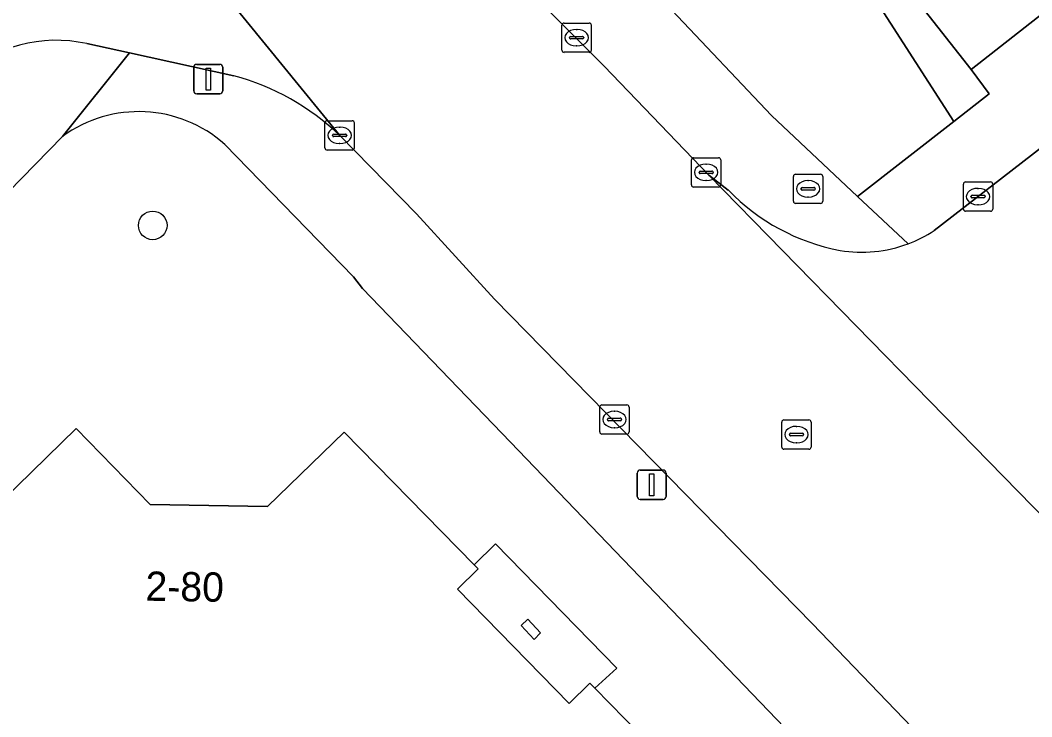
# Model space of a CAD drawing. Extents: x 159217 to 160349, y 381246 to 382172.
# Drawn here: x 159551.64 to 159586.14, y 381526.69 to 381550.47 of the extents above; entities that cross this region are included whole.
import ezdxf

# ---------------------------------------------------------------- set-up
doc = ezdxf.new("R2010")
doc.units = 0
for name, color, linetype in [('IMGEO_Boom', 7, 'Continuous'), ('IMGEO_Brandkraan', 7, 'Continuous'), ('IMGEO_Erf', 7, 'Continuous'), ('IMGEO_Fietspad_gesloten', 7, 'Continuous'), ('IMGEO_Groenvoorziening', 7, 'Continuous'), ('IMGEO_Haag', 7, 'Continuous'), ('IMGEO_Kolk', 7, 'Continuous'), ('IMGEO_Lichtmast', 7, 'Continuous'), ('IMGEO_Pand', 7, 'Continuous'), ('IMGEO_Pand_nummerreeks', 7, 'Continuous'), ('IMGEO_Rijbaan_lokaal_gesloten', 7, 'Continuous'), ('IMGEO_Rijbaan_lokaal_open', 7, 'Continuous'), ('IMGEO_Rioolput', 7, 'Continuous'), ('IMGEO_Voetpad_open', 7, 'Continuous')]:
    doc.layers.add(name, color=color, linetype=linetype)

msp = doc.modelspace()

# ---------------------------------------------------------------- linework, layer by layer
at = {"layer": 'IMGEO_Boom'}
msp.add_circle((159556.157, 381543.464), 0.489, dxfattribs=at)
at = {"layer": 'IMGEO_Brandkraan'}
for p, q in [((159578.01, 381544.286), (159578.01, 381545.138)), ((159578.085, 381545.212), (159578.937, 381545.212)), ((159578.498, 381544.992), (159578.523, 381544.992)), ((159579.011, 381545.138), (159579.011, 381544.286)), ((159578.269, 381544.706), (159578.269, 381544.718)), ((159578.707, 381544.669), (159578.309, 381544.669)), ((159578.312, 381544.755), (159578.71, 381544.755)), ((159578.753, 381544.718), (159578.753, 381544.706)), ((159578.937, 381544.212), (159578.085, 381544.212)), ((159578.521, 381544.432), (159578.496, 381544.432))]:
    msp.add_line(p, q, dxfattribs=at)
for points in [[(159578.01, 381544.286), (159578.01, 381545.138)], [(159578.085, 381545.212), (159578.937, 381545.212)], [(159579.011, 381545.138), (159579.011, 381544.286)], [(159578.937, 381544.212), (159578.085, 381544.212)]]:
    msp.add_lwpolyline(points, dxfattribs=at)
for centre, radius, start, end in [((159578.087, 381545.136), 0.0765, 91.552, 178.448), ((159578.087, 381545.136), 0.0765, 91.552, 178.448), ((159578.935, 381545.136), 0.0765, 1.552, 88.448), ((159578.935, 381545.136), 0.0765, 1.552, 88.448), ((159578.309, 381544.715), 0.0403, 85.8775, 175.7526), ((159578.306, 381544.705), 0.0366, 178.938, 274.7102), ((159578.71, 381544.712), 0.043, 264.8664, 352.4533), ((159578.714, 381544.717), 0.0386, 1.7309, 96.639), ((159578.087, 381544.288), 0.0765, 181.552, 268.448), ((159578.087, 381544.288), 0.0765, 181.552, 268.448), ((159578.935, 381544.288), 0.0765, 271.552, 358.448), ((159578.935, 381544.288), 0.0765, 271.552, 358.448)]:
    msp.add_arc(centre, radius, start, end, dxfattribs=at)
for centre, major_axis, ratio, start_param, end_param in [((159578.497, 381544.712), (-0.387, 0.002), 0.722429, 4.712389, 7.853982), ((159578.522, 381544.712), (-0.39, 0.002), 0.717154, 1.570796, 4.712389)]:
    msp.add_ellipse(centre, major_axis=major_axis, ratio=ratio, start_param=start_param, end_param=end_param, dxfattribs=at)
at = {"layer": 'IMGEO_Erf'}
for points in [[(159553.08, 381546.504), (159547.055, 381540.335)], [(159599.397, 381500), (159599.498, 381500.339), (159599.569, 381500.686), (159599.609, 381501.038), (159599.616, 381501.392), (159599.593, 381501.746), (159599.537, 381502.095), (159599.451, 381502.439), (159599.334, 381502.773), (159599.188, 381503.096), (159599.014, 381503.404), (159598.813, 381503.695), (159598.586, 381503.968), (159598.538, 381504.02), (159597.784, 381504.824), (159590.258, 381513.08), (159579.357, 381524.607), (159568.355, 381536.063), (159563.311, 381541.305), (159563.005, 381541.713), (159558.611, 381546.23)], [(159549.012, 381532.1), (159553.55, 381536.531), (159556.072, 381533.93), (159560.073, 381533.872), (159562.681, 381536.409), (159567.124, 381531.873), (159567.853, 381532.593), (159571.987, 381528.35), (159571.239, 381527.664), (159579.938, 381518.763), (159579.276, 381518.08), (159583.114, 381514.253), (159583.728, 381514.876), (159588.153, 381510.339), (159588.919, 381511.059), (159590.957, 381508.968), (159590.2, 381508.265), (159594.596, 381503.795)]]:
    msp.add_lwpolyline(points, dxfattribs=at)
for points in [[(159567.853, 381532.593), (159567.124, 381531.873), (159567.256, 381531.738), (159566.553, 381531.041), (159570.364, 381527.142), (159571.07, 381527.837), (159571.239, 381527.664), (159571.987, 381528.35)], [(159568.955, 381530.016), (159569.389, 381529.552), (159569.166, 381529.324), (159568.721, 381529.802)]]:
    msp.add_lwpolyline(points, close=True, dxfattribs=at)
msp.add_arc((159555.676, 381542.937), 4.411, 48.2858, 126.0421, dxfattribs=at)
at = {"layer": 'IMGEO_Fietspad_gesloten'}
for points in [[(159562.533, 381546.538), (159558.685, 381551.263)], [(159553.908, 381549.669), (159555.359, 381549.351), (159558.919, 381548.568)]]:
    msp.add_lwpolyline(points, dxfattribs=at)
for centre, radius, start, end in [((159552.866, 381545.016), 4.769, 77.3835, 133.0545), ((159556.823, 381540.604), 8.235, 46.1004, 75.2534)]:
    msp.add_arc(centre, radius, start, end, dxfattribs=at)
at = {"layer": 'IMGEO_Groenvoorziening'}
for points in [[(159576.056, 381556.935), (159580.454, 381551.717), (159583.479, 381547.014), (159584.683, 381547.956), (159584.068, 381548.786), (159577.496, 381557.149), (159577.049, 381557.715)], [(159573.858, 381550.817), (159577.265, 381547.216), (159580.2, 381544.451), (159583.479, 381547.014), (159580.454, 381551.717), (159576.056, 381556.935), (159573.741, 381555.137), (159571.415, 381553.33)]]:
    msp.add_lwpolyline(points, close=True, dxfattribs=at)
at = {"layer": 'IMGEO_Haag'}
for points in [[(159553.08, 381546.504), (159547.055, 381540.335)], [(159599.397, 381500), (159599.498, 381500.339), (159599.569, 381500.686), (159599.609, 381501.038), (159599.616, 381501.392), (159599.593, 381501.746), (159599.537, 381502.095), (159599.451, 381502.439), (159599.334, 381502.773), (159599.188, 381503.096), (159599.014, 381503.404), (159598.813, 381503.695), (159598.586, 381503.968), (159598.538, 381504.02), (159597.784, 381504.824), (159590.258, 381513.08), (159579.357, 381524.607), (159568.355, 381536.063), (159563.311, 381541.305), (159563.005, 381541.713), (159558.611, 381546.23)], [(159549.012, 381532.1), (159553.55, 381536.531), (159556.072, 381533.93), (159560.073, 381533.872), (159562.681, 381536.409), (159567.124, 381531.873), (159567.853, 381532.593), (159571.987, 381528.35), (159571.239, 381527.664), (159579.938, 381518.763), (159579.276, 381518.08), (159583.114, 381514.253), (159583.728, 381514.876), (159588.153, 381510.339), (159588.919, 381511.059), (159590.957, 381508.968), (159590.2, 381508.265), (159594.596, 381503.795)]]:
    msp.add_lwpolyline(points, dxfattribs=at)
msp.add_arc((159555.676, 381542.937), 4.411, 48.2858, 126.0421, dxfattribs=at)
at = {"layer": 'IMGEO_Kolk'}
for p, q in [((159570.116, 381549.447), (159570.116, 381550.299)), ((159570.191, 381550.373), (159571.043, 381550.373)), ((159570.604, 381550.153), (159570.629, 381550.153)), ((159571.117, 381550.299), (159571.117, 381549.447)), ((159570.375, 381549.867), (159570.375, 381549.879)), ((159570.813, 381549.83), (159570.415, 381549.83)), ((159570.418, 381549.916), (159570.816, 381549.916)), ((159570.859, 381549.879), (159570.859, 381549.867)), ((159570.627, 381549.593), (159570.602, 381549.593)), ((159571.043, 381549.373), (159570.191, 381549.373)), ((159562.107, 381547.038), (159562.959, 381547.038)), ((159562.032, 381546.112), (159562.032, 381546.964)), ((159562.52, 381546.818), (159562.545, 381546.818)), ((159563.033, 381546.964), (159563.033, 381546.112)), ((159562.291, 381546.532), (159562.291, 381546.544)), ((159562.729, 381546.495), (159562.331, 381546.495)), ((159562.334, 381546.581), (159562.732, 381546.581)), ((159562.775, 381546.544), (159562.775, 381546.532)), ((159562.959, 381546.038), (159562.107, 381546.038)), ((159562.543, 381546.258), (159562.518, 381546.258)), ((159574.532, 381544.849), (159574.532, 381545.701)), ((159574.607, 381545.775), (159575.459, 381545.775)), ((159575.533, 381545.701), (159575.533, 381544.849)), ((159574.791, 381545.269), (159574.791, 381545.281)), ((159574.834, 381545.318), (159575.232, 381545.318)), ((159575.02, 381545.555), (159575.045, 381545.555)), ((159575.275, 381545.281), (159575.275, 381545.269)), ((159575.229, 381545.232), (159574.831, 381545.232)), ((159575.043, 381544.995), (159575.018, 381544.995)), ((159583.882, 381544.948), (159584.734, 381544.948)), ((159575.459, 381544.775), (159574.607, 381544.775)), ((159583.807, 381544.022), (159583.807, 381544.874)), ((159584.295, 381544.728), (159584.32, 381544.728)), ((159584.808, 381544.874), (159584.808, 381544.022)), ((159584.066, 381544.442), (159584.066, 381544.454)), ((159584.504, 381544.405), (159584.106, 381544.405)), ((159584.109, 381544.491), (159584.507, 381544.491)), ((159584.55, 381544.454), (159584.55, 381544.442)), ((159584.734, 381543.948), (159583.882, 381543.948)), ((159584.318, 381544.168), (159584.293, 381544.168)), ((159571.481, 381537.338), (159572.333, 381537.338)), ((159571.406, 381536.412), (159571.406, 381537.264)), ((159571.894, 381537.118), (159571.919, 381537.118)), ((159572.407, 381537.264), (159572.407, 381536.412)), ((159571.665, 381536.832), (159571.665, 381536.844)), ((159572.103, 381536.795), (159571.705, 381536.795)), ((159571.708, 381536.881), (159572.106, 381536.881)), ((159572.149, 381536.844), (159572.149, 381536.832)), ((159572.333, 381536.338), (159571.481, 381536.338)), ((159571.917, 381536.558), (159571.892, 381536.558))]:
    msp.add_line(p, q, dxfattribs=at)
for points in [[(159570.116, 381549.447), (159570.116, 381550.299)], [(159570.191, 381550.373), (159571.043, 381550.373)], [(159571.117, 381550.299), (159571.117, 381549.447)], [(159571.043, 381549.373), (159570.191, 381549.373)], [(159562.107, 381547.038), (159562.959, 381547.038)], [(159562.032, 381546.112), (159562.032, 381546.964)], [(159563.033, 381546.964), (159563.033, 381546.112)], [(159562.959, 381546.038), (159562.107, 381546.038)], [(159574.532, 381544.849), (159574.532, 381545.701)], [(159574.607, 381545.775), (159575.459, 381545.775)], [(159575.533, 381545.701), (159575.533, 381544.849)], [(159583.882, 381544.948), (159584.734, 381544.948)], [(159575.459, 381544.775), (159574.607, 381544.775)], [(159583.807, 381544.022), (159583.807, 381544.874)], [(159584.808, 381544.874), (159584.808, 381544.022)], [(159584.734, 381543.948), (159583.882, 381543.948)], [(159571.481, 381537.338), (159572.333, 381537.338)], [(159571.406, 381536.412), (159571.406, 381537.264)], [(159572.407, 381537.264), (159572.407, 381536.412)], [(159572.333, 381536.338), (159571.481, 381536.338)]]:
    msp.add_lwpolyline(points, dxfattribs=at)
for centre, radius, start, end in [((159570.193, 381550.297), 0.0765, 91.552, 178.448), ((159570.193, 381550.297), 0.0765, 91.552, 178.448), ((159571.041, 381550.297), 0.0765, 1.552, 88.448), ((159571.041, 381550.297), 0.0765, 1.552, 88.448), ((159570.415, 381549.876), 0.0403, 85.8775, 175.7526), ((159570.412, 381549.866), 0.0366, 178.938, 274.7102), ((159570.816, 381549.873), 0.043, 264.8664, 352.4533), ((159570.82, 381549.878), 0.0386, 1.7309, 96.639), ((159570.193, 381549.449), 0.0765, 181.552, 268.448), ((159570.193, 381549.449), 0.0765, 181.552, 268.448), ((159571.041, 381549.449), 0.0765, 271.552, 358.448), ((159571.041, 381549.449), 0.0765, 271.552, 358.448), ((159562.109, 381546.962), 0.0765, 91.552, 178.448), ((159562.109, 381546.962), 0.0765, 91.552, 178.448), ((159562.957, 381546.962), 0.0765, 1.552, 88.448), ((159562.957, 381546.962), 0.0765, 1.552, 88.448), ((159562.331, 381546.541), 0.0403, 85.8775, 175.7526), ((159562.328, 381546.531), 0.0366, 178.938, 274.7102), ((159562.732, 381546.538), 0.043, 264.8664, 352.4533), ((159562.736, 381546.543), 0.0386, 1.7309, 96.639), ((159562.109, 381546.114), 0.0765, 181.552, 268.448), ((159562.109, 381546.114), 0.0765, 181.552, 268.448), ((159562.957, 381546.114), 0.0765, 271.552, 358.448), ((159562.957, 381546.114), 0.0765, 271.552, 358.448), ((159574.609, 381545.699), 0.0765, 91.552, 178.448), ((159574.609, 381545.699), 0.0765, 91.552, 178.448), ((159575.457, 381545.699), 0.0765, 1.552, 88.448), ((159575.457, 381545.699), 0.0765, 1.552, 88.448), ((159574.831, 381545.278), 0.0403, 85.8775, 175.7526), ((159574.828, 381545.268), 0.0366, 178.938, 274.7102), ((159575.232, 381545.275), 0.043, 264.8664, 352.4533), ((159575.236, 381545.28), 0.0386, 1.7309, 96.639), ((159583.884, 381544.872), 0.0765, 91.552, 178.448), ((159583.884, 381544.872), 0.0765, 91.552, 178.448), ((159584.732, 381544.872), 0.0765, 1.552, 88.448), ((159584.732, 381544.872), 0.0765, 1.552, 88.448), ((159574.609, 381544.851), 0.0765, 181.552, 268.448), ((159574.609, 381544.851), 0.0765, 181.552, 268.448), ((159575.457, 381544.851), 0.0765, 271.552, 358.448), ((159575.457, 381544.851), 0.0765, 271.552, 358.448), ((159584.106, 381544.451), 0.0403, 85.8775, 175.7526), ((159584.103, 381544.441), 0.0366, 178.938, 274.7102), ((159584.507, 381544.448), 0.043, 264.8664, 352.4533), ((159584.511, 381544.453), 0.0386, 1.7309, 96.639), ((159583.884, 381544.024), 0.0765, 181.552, 268.448), ((159583.884, 381544.024), 0.0765, 181.552, 268.448), ((159584.732, 381544.024), 0.0765, 271.552, 358.448), ((159584.732, 381544.024), 0.0765, 271.552, 358.448), ((159571.483, 381537.262), 0.0765, 91.552, 178.448), ((159571.483, 381537.262), 0.0765, 91.552, 178.448), ((159572.331, 381537.262), 0.0765, 1.552, 88.448), ((159572.331, 381537.262), 0.0765, 1.552, 88.448), ((159571.705, 381536.841), 0.0403, 85.8775, 175.7526), ((159571.702, 381536.831), 0.0366, 178.938, 274.7102), ((159572.106, 381536.838), 0.043, 264.8664, 352.4533), ((159572.11, 381536.843), 0.0386, 1.7309, 96.639), ((159571.483, 381536.414), 0.0765, 181.552, 268.448), ((159571.483, 381536.414), 0.0765, 181.552, 268.448), ((159572.331, 381536.414), 0.0765, 271.552, 358.448), ((159572.331, 381536.414), 0.0765, 271.552, 358.448)]:
    msp.add_arc(centre, radius, start, end, dxfattribs=at)
for centre, major_axis, ratio, start_param, end_param in [((159570.603, 381549.873), (-0.387, 0.002), 0.722429, 4.712389, 7.853982), ((159570.628, 381549.873), (-0.39, 0.002), 0.717154, 1.570796, 4.712389), ((159562.519, 381546.538), (-0.387, 0.002), 0.722429, 4.712389, 7.853982), ((159562.544, 381546.538), (-0.39, 0.002), 0.717154, 1.570796, 4.712389), ((159575.019, 381545.275), (-0.387, 0.002), 0.722429, 4.712389, 7.853982), ((159575.044, 381545.275), (-0.39, 0.002), 0.717154, 1.570796, 4.712389), ((159584.294, 381544.448), (-0.387, 0.002), 0.722429, 4.712389, 7.853982), ((159584.319, 381544.448), (-0.39, 0.002), 0.717154, 1.570796, 4.712389), ((159571.893, 381536.838), (-0.387, 0.002), 0.722429, 4.712389, 7.853982), ((159571.918, 381536.838), (-0.39, 0.002), 0.717154, 1.570796, 4.712389)]:
    msp.add_ellipse(centre, major_axis=major_axis, ratio=ratio, start_param=start_param, end_param=end_param, dxfattribs=at)
at = {"layer": 'IMGEO_Lichtmast'}
for p, q in [((159557.556, 381548.061), (159557.556, 381548.861)), ((159557.556, 381548.861), (159557.556, 381548.061)), ((159557.656, 381548.961), (159558.446, 381548.961)), ((159558.446, 381548.961), (159557.656, 381548.961)), ((159558.546, 381548.861), (159558.546, 381548.061)), ((159558.546, 381548.061), (159558.546, 381548.861)), ((159558.446, 381547.961), (159557.656, 381547.961)), ((159557.656, 381547.961), (159558.446, 381547.961)), ((159572.68, 381534.211), (159572.68, 381535.011)), ((159572.68, 381535.011), (159572.68, 381534.211)), ((159572.78, 381535.111), (159573.57, 381535.111)), ((159573.57, 381535.111), (159572.78, 381535.111)), ((159573.67, 381535.011), (159573.67, 381534.211)), ((159573.67, 381534.211), (159573.67, 381535.011)), ((159573.57, 381534.111), (159572.78, 381534.111)), ((159572.78, 381534.111), (159573.57, 381534.111))]:
    msp.add_line(p, q, dxfattribs=at)
for points in [[(159557.976, 381548.836), (159558.126, 381548.836), (159558.126, 381548.086), (159557.976, 381548.086), (159557.976, 381548.836)], [(159573.1, 381534.986), (159573.25, 381534.986), (159573.25, 381534.236), (159573.1, 381534.236), (159573.1, 381534.986)]]:
    msp.add_lwpolyline(points, dxfattribs=at)
for centre, start, end in [((159557.656, 381548.861), 90, 180), ((159557.656, 381548.861), 90, 180), ((159558.446, 381548.861), 0, 90), ((159558.446, 381548.861), 360, 90), ((159557.656, 381548.061), 180, 270), ((159557.656, 381548.061), 180, 270), ((159558.446, 381548.061), 270, 0), ((159558.446, 381548.061), 270, 0), ((159572.78, 381535.011), 90, 180), ((159572.78, 381535.011), 90, 180), ((159573.57, 381535.011), 0, 90), ((159573.57, 381535.011), 360, 90), ((159572.78, 381534.211), 180, 270), ((159572.78, 381534.211), 180, 270), ((159573.57, 381534.211), 270, 0), ((159573.57, 381534.211), 270, 0)]:
    msp.add_arc(centre, 0.1, start, end, dxfattribs=at)
at = {"layer": 'IMGEO_Pand'}
for points in [[(159595.862, 381558.054), (159589.29, 381566.417), (159577.496, 381557.149), (159584.068, 381548.786)], [(159569.166, 381529.324), (159569.389, 381529.552), (159568.955, 381530.016), (159568.721, 381529.802)]]:
    msp.add_lwpolyline(points, close=True, dxfattribs=at)
msp.add_lwpolyline([(159594.596, 381503.795), (159590.2, 381508.265), (159590.031, 381508.437), (159589.33, 381507.751), (159587.659, 381509.459), (159588.342, 381510.146), (159588.153, 381510.339), (159583.728, 381514.876), (159583.114, 381514.253), (159579.276, 381518.08), (159579.938, 381518.763), (159571.239, 381527.664), (159571.07, 381527.837), (159570.364, 381527.142), (159566.553, 381531.041), (159567.256, 381531.738), (159567.124, 381531.873), (159562.681, 381536.409), (159560.073, 381533.872), (159556.072, 381533.93), (159553.55, 381536.531), (159549.012, 381532.1)], dxfattribs=at)
at = {"layer": 'IMGEO_Rijbaan_lokaal_gesloten'}
for points in [[(159608.412, 381509.965), (159593.122, 381526.476), (159587.692, 381532.316), (159575.127, 381545.176), (159571.55, 381548.905), (159568.481, 381551.989), (159568.319, 381552.145), (159567.588, 381552.808), (159564.187, 381555.775)], [(159558.685, 381551.263), (159562.533, 381546.538), (159565.152, 381543.854), (159567.81, 381540.95), (159578.666, 381529.864), (159592.512, 381515.439), (159599.596, 381507.693), (159601.31, 381505.606), (159602.056, 381504.314), (159602.178, 381504.004), (159602.351, 381503.454), (159602.474, 381502.891), (159602.546, 381502.319), (159602.548, 381502.232), (159610.359, 381508.766), (159609.93, 381508.934), (159609.517, 381509.14), (159609.125, 381509.381), (159608.755, 381509.657), (159608.412, 381509.965)]]:
    msp.add_lwpolyline(points, dxfattribs=at)
at = {"layer": 'IMGEO_Rijbaan_lokaal_open'}
for points in [[(159623.373, 381575.125), (159611.28, 381565.67), (159586.487, 381546.139), (159582.812, 381543.285)], [(159575.79, 381544.664), (159575.127, 381545.176), (159587.692, 381532.316)]]:
    msp.add_lwpolyline(points, dxfattribs=at)
for centre, radius, start, end in [((159580.933, 381549.645), 7.159, 224.0833, 259.2955), ((159580.364, 381547.025), 4.47, 290.3853, 303.2068), ((159580.341, 381547.055), 4.506, 260.5677, 290.5205)]:
    msp.add_arc(centre, radius, start, end, dxfattribs=at)
at = {"layer": 'IMGEO_Rioolput'}
for p, q in [((159577.613, 381535.897), (159577.613, 381536.749)), ((159577.688, 381536.823), (159578.54, 381536.823)), ((159578.614, 381536.749), (159578.614, 381535.897)), ((159577.872, 381536.317), (159577.872, 381536.329)), ((159578.31, 381536.28), (159577.912, 381536.28)), ((159577.915, 381536.366), (159578.313, 381536.366)), ((159578.101, 381536.603), (159578.126, 381536.603)), ((159578.356, 381536.329), (159578.356, 381536.317)), ((159578.124, 381536.043), (159578.099, 381536.043)), ((159578.54, 381535.823), (159577.688, 381535.823))]:
    msp.add_line(p, q, dxfattribs=at)
for points in [[(159577.613, 381535.897), (159577.613, 381536.749)], [(159577.688, 381536.823), (159578.54, 381536.823)], [(159578.614, 381536.749), (159578.614, 381535.897)], [(159578.54, 381535.823), (159577.688, 381535.823)]]:
    msp.add_lwpolyline(points, dxfattribs=at)
for centre, radius, start, end in [((159577.69, 381536.747), 0.0765, 91.552, 178.448), ((159577.69, 381536.747), 0.0765, 91.552, 178.448), ((159578.538, 381536.747), 0.0765, 1.552, 88.448), ((159578.538, 381536.747), 0.0765, 1.552, 88.448), ((159577.912, 381536.326), 0.0403, 85.8775, 175.7526), ((159577.909, 381536.316), 0.0366, 178.938, 274.7102), ((159578.313, 381536.323), 0.043, 264.8664, 352.4533), ((159578.317, 381536.328), 0.0386, 1.7309, 96.639), ((159577.69, 381535.899), 0.0765, 181.552, 268.448), ((159577.69, 381535.899), 0.0765, 181.552, 268.448), ((159578.538, 381535.899), 0.0765, 271.552, 358.448), ((159578.538, 381535.899), 0.0765, 271.552, 358.448)]:
    msp.add_arc(centre, radius, start, end, dxfattribs=at)
for centre, major_axis, ratio, start_param, end_param in [((159578.1, 381536.323), (-0.387, 0.002), 0.722429, 4.712389, 7.853982), ((159578.125, 381536.323), (-0.39, 0.002), 0.717154, 1.570796, 4.712389)]:
    msp.add_ellipse(centre, major_axis=major_axis, ratio=ratio, start_param=start_param, end_param=end_param, dxfattribs=at)
at = {"layer": 'IMGEO_Voetpad_open'}
for points in [[(159641.423, 381583.314), (159639.994, 381585.075), (159635.089, 381581.22), (159633.188, 381583.639), (159631.368, 381585.955), (159619.451, 381576.59), (159607.656, 381567.322), (159595.862, 381558.054), (159584.068, 381548.786), (159584.683, 381547.956), (159583.479, 381547.014), (159580.2, 381544.451), (159581.921, 381542.835)], [(159582.812, 381543.285), (159586.487, 381546.139), (159611.28, 381565.67), (159623.373, 381575.125)], [(159573.858, 381550.817), (159571.415, 381553.33), (159569.753, 381555.039), (159567.621, 381552.983), (159567.916, 381552.646), (159568.481, 381551.989), (159571.55, 381548.905), (159575.127, 381545.176), (159575.79, 381544.664)], [(159581.921, 381542.835), (159580.2, 381544.451), (159577.265, 381547.216), (159573.858, 381550.817)], [(159464.894, 381461.532), (159469.709, 381454.515), (159471.167, 381455.42), (159466.195, 381462.617), (159476.932, 381472.529), (159482.538, 381477.704), (159484.561, 381479.657), (159488.152, 381482.991), (159500, 381494.116), (159503.599, 381497.515), (159505.169, 381499.013), (159506.202, 381500), (159516.14, 381509.604), (159520.094, 381513.425), (159535.613, 381528.787), (159542.408, 381535.643), (159547.055, 381540.335), (159553.08, 381546.504), (159555.359, 381549.351), (159553.908, 381549.669)], [(159558.919, 381548.568), (159555.359, 381549.351), (159553.08, 381546.504)], [(159592.512, 381515.439), (159578.666, 381529.864), (159567.81, 381540.95), (159565.152, 381543.854), (159562.533, 381546.538)], [(159558.611, 381546.23), (159563.005, 381541.713), (159563.311, 381541.305), (159568.355, 381536.063), (159579.357, 381524.607), (159590.258, 381513.08), (159597.784, 381504.824), (159598.538, 381504.02), (159598.586, 381503.968), (159598.813, 381503.695), (159599.014, 381503.404), (159599.188, 381503.096), (159599.334, 381502.773), (159599.451, 381502.439), (159599.537, 381502.095), (159599.593, 381501.746), (159599.616, 381501.392), (159599.609, 381501.038), (159599.569, 381500.686), (159599.498, 381500.339), (159599.397, 381500)]]:
    msp.add_lwpolyline(points, dxfattribs=at)
for centre, radius, start, end in [((159552.866, 381545.016), 4.769, 77.3835, 133.0545), ((159556.823, 381540.604), 8.235, 46.1004, 75.2534), ((159555.676, 381542.937), 4.411, 48.2858, 126.0421), ((159580.933, 381549.645), 7.159, 224.0833, 259.2955), ((159580.364, 381547.025), 4.47, 290.3853, 303.2068), ((159580.341, 381547.055), 4.506, 260.5677, 290.5205)]:
    msp.add_arc(centre, radius, start, end, dxfattribs=at)

# ---------------------------------------------------------------- texts
at = {"layer": 'IMGEO_Pand_nummerreeks'}
msp.add_text('2-80', height=1, rotation=359.1695, dxfattribs=at).set_placement((159555.903, 381530.651))

doc.saveas('drawing.dxf')
